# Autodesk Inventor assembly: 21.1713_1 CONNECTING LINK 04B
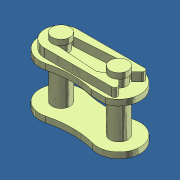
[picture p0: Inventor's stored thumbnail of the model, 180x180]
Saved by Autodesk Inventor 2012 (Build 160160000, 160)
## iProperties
Created: 2016-02
Part Number: 21.1713_1 CONNECTING LINK 04B
Document SubType Name: Assembly
Designer: Admin
Author: Admin
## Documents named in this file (4)
- C:\Andys Backup Data\ANDY'S INVENTOR\INVENTOR LIBRARIES\PARTS LIBRARY\PREASSEMBLED ELEMENTS FOR LIFTING AND SLIDING DOORS\21.1713_1 CONNECTING LINK 04B.iam
- C:\Andys Backup Data\ANDY'S INVENTOR\INVENTOR LIBRARIES\PARTS LIBRARY\PREASSEMBLED ELEMENTS FOR LIFTING AND SLIDING DOORS\SUBCOMPONENTS\21.1713_1 CONNECTING LINK 04B BODY WITH PINS.ipt
- C:\Andys Backup Data\ANDY'S INVENTOR\INVENTOR LIBRARIES\PARTS LIBRARY\PREASSEMBLED ELEMENTS FOR LIFTING AND SLIDING DOORS\SUBCOMPONENTS\21.1713_1 CONNECTING LINK 04B SIDE PLATE.ipt
- C:\Andys Backup Data\ANDY'S INVENTOR\INVENTOR LIBRARIES\PARTS LIBRARY\PREASSEMBLED ELEMENTS FOR LIFTING AND SLIDING DOORS\SUBCOMPONENTS\21.1713_1 CONNECTING LINK 04B CLIP.ipt
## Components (3 placed, 3 different names)
1. 21.1713_1 CONNECTING LINK 04B BODY WITH PINS:1 — Mate:2, Insert:1, Mate:3, Mate:4, Mate:5
2. 21.1713_1 CONNECTING LINK 04B SIDE PLATE:1 — Mate:2, Insert:1
3. 21.1713_1 CONNECTING LINK 04B CLIP:1 — Mate:3, Mate:4, Mate:5
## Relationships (5: Mate 4, Insert 1)
- Mate:2: 21.1713_1 CONNECTING LINK 04B BODY WITH PINS:1 ↔ 21.1713_1 CONNECTING LINK 04B SIDE PLATE:1
- Insert:1: 21.1713_1 CONNECTING LINK 04B BODY WITH PINS:1 ↔ 21.1713_1 CONNECTING LINK 04B SIDE PLATE:1
- Mate:3: 21.1713_1 CONNECTING LINK 04B BODY WITH PINS:1 ↔ 21.1713_1 CONNECTING LINK 04B CLIP:1
- Mate:4: 21.1713_1 CONNECTING LINK 04B BODY WITH PINS:1 ↔ 21.1713_1 CONNECTING LINK 04B CLIP:1
- Mate:5: 21.1713_1 CONNECTING LINK 04B BODY WITH PINS:1 ↔ 21.1713_1 CONNECTING LINK 04B CLIP:1
